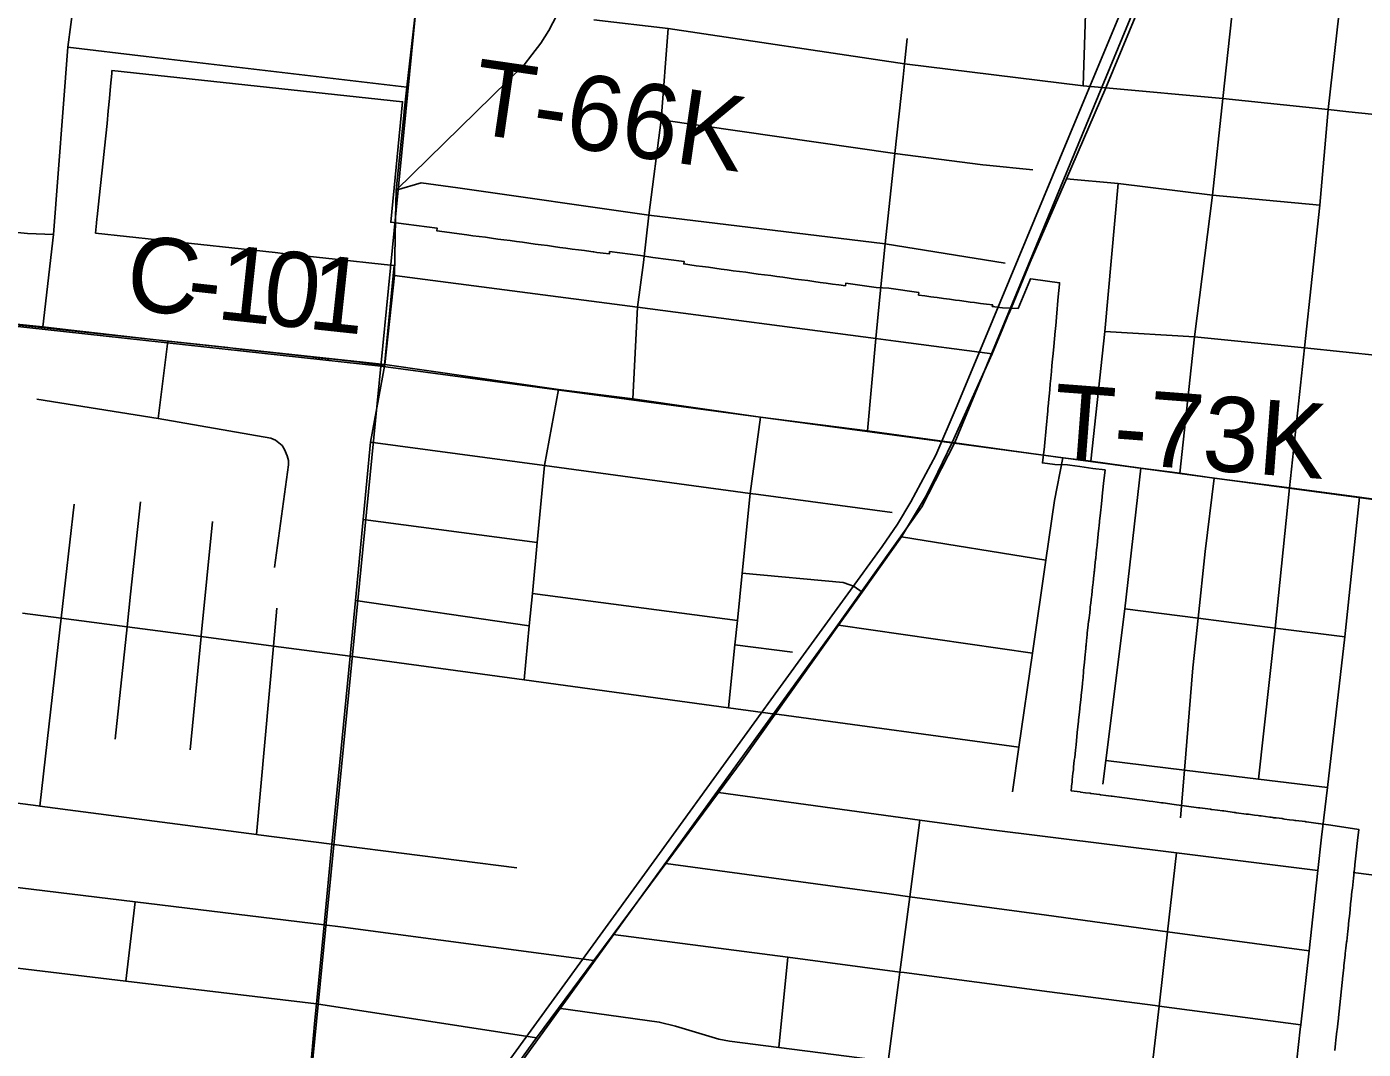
# Model space of a CAD drawing. Extents: x 0 to 34, y -3.9 to 26.2.
# Drawn here: x 5.706 to 6.718, y 17.55 to 18.325 of the extents above; entities that cross this region are included whole.
import ezdxf

# ---------------------------------------------------------------- set-up
doc = ezdxf.new("R2010")
doc.units = 0
for name, color, linetype in [('GM_X_City_Street', 7, 'Continuous'), ('GM_X_Corporation', 7, 'Continuous'), ('GM_X_County_Road', 7, 'Continuous'), ('GM_X_County_Road_Text', 7, 'Continuous'), ('GM_X_Rail_Line', 7, 'Continuous'), ('GM_X_Section', 7, 'Continuous'), ('GM_X_Township_Road', 7, 'Continuous'), ('GM_X_Township_Road_Text', 7, 'Continuous')]:
    doc.layers.add(name, color=color, linetype=linetype)

msp = doc.modelspace()

# ---------------------------------------------------------------- linework, layer by layer
at = {"layer": 'GM_X_City_Street'}
for p, q in [((5.8055, 18.0282), (5.8129, 18.0866)), ((5.9608, 17.9517), (6.0925, 17.9341)), ((6.3681, 17.9385), (6.4774, 17.9209)), ((5.9549, 17.8904), (6.0865, 17.8712)), ((6.0888, 17.8955), (6.244, 17.8752)), ((6.3205, 17.8715), (6.4673, 17.8504)), ((6.2421, 17.8567), (6.2856, 17.8512)), ((5.7812, 17.602), (5.7882, 17.6622)), ((6.2754, 17.5519), (6.2821, 17.6201))]:
    msp.add_line(p, q, dxfattribs=at)
for points in [[(6.1649, 18.0429), (6.1685, 18.1123), (6.173, 18.1463)], [(5.9844, 18.1365), (6.1685, 18.1123), (6.3487, 18.0887), (6.364, 18.0867), (6.4369, 18.0771)], [(6.3426, 18.0187), (6.3487, 18.0887), (6.3517, 18.1202)], [(6.0826, 17.8302), (6.0865, 17.8712), (6.0888, 17.8955), (6.0925, 17.9341), (6.098, 17.9924), (6.1086, 18.05)], [(5.7137, 18.0427), (5.8055, 18.0282), (5.8908, 18.0132), (5.8944, 18.0116), (5.8993, 18.0076), (5.9012, 18.0046), (5.9033, 17.9998), (5.9042, 17.9964), (5.9042, 17.993), (5.8936, 17.9152)], [(6.2373, 17.8091), (6.2421, 17.8567), (6.244, 17.8752), (6.2476, 17.911), (6.2537, 17.9713), (6.2615, 18.0292)], [(5.9664, 18.0102), (6.098, 17.9924), (6.2537, 17.9713), (6.2599, 17.9705), (6.3612, 17.9568)], [(6.4904, 17.9983), (6.4839, 17.9661), (6.4774, 17.9209), (6.4673, 17.8504), (6.4571, 17.7791), (6.4523, 17.7453)], [(5.716, 17.7346), (5.7312, 17.868), (5.7322, 17.8768), (5.742, 17.9633)], [(5.7731, 17.7852), (5.7821, 17.8703), (5.7847, 17.8951), (5.7921, 17.965)], [(5.8298, 17.7772), (5.8382, 17.8629), (5.8382, 17.8637), (5.8467, 17.9502)], [(6.2476, 17.911), (6.3241, 17.904), (6.329, 17.9022), (6.3325, 17.9008), (6.3384, 17.8967)], [(5.7029, 17.8806), (5.7322, 17.8768), (5.7821, 17.8703), (5.8382, 17.8629), (5.8929, 17.8558), (5.9508, 17.8482), (6.0826, 17.8302), (6.2373, 17.8091), (6.2727, 17.8042), (6.2756, 17.8039), (6.4571, 17.7791)], [(5.88, 17.713), (5.8929, 17.8558), (5.8955, 17.8844)], [(5.4423, 17.7675), (5.5662, 17.7527), (5.6896, 17.7381), (5.7147, 17.7348), (5.716, 17.7346), (5.88, 17.713), (5.8816, 17.7128), (5.9371, 17.7057), (5.9461, 17.7046), (6.077, 17.6878)], [(6.2298, 17.7449), (6.3821, 17.7239), (6.4324, 17.717), (6.5764, 17.6991), (6.6834, 17.6857)], [(6.3581, 17.5413), (6.367, 17.6089), (6.3745, 17.666), (6.3821, 17.7239)], [(5.438, 17.7046), (5.5591, 17.6899), (5.6908, 17.674), (5.7882, 17.6622), (5.9312, 17.6448), (5.9435, 17.6432), (6.1353, 17.6176)], [(6.6593, 17.4687), (6.663, 17.5023), (6.6636, 17.5075), (6.6701, 17.5656), (6.6704, 17.569), (6.6767, 17.6249), (6.6834, 17.6857), (6.6862, 17.7111)], [(6.549, 17.4743), (6.5555, 17.5161), (6.5632, 17.5831), (6.5696, 17.6395), (6.5764, 17.6991)], [(6.1899, 17.6911), (6.3588, 17.6682), (6.3745, 17.666), (6.478, 17.6519), (6.5696, 17.6395), (6.6767, 17.6249)], [(5.4304, 17.6437), (5.5522, 17.6292), (5.6971, 17.612), (5.7055, 17.611), (5.7812, 17.602), (5.9254, 17.5848), (6.092, 17.5592)], [(6.15, 17.6374), (6.2821, 17.6201), (6.367, 17.6089), (6.3702, 17.6085), (6.4803, 17.594), (6.5603, 17.5835), (6.5632, 17.5831), (6.6704, 17.569)], [(6.1086, 17.5816), (6.1848, 17.571), (6.1972, 17.568), (6.23, 17.558), (6.2379, 17.5567), (6.2754, 17.5519), (6.3581, 17.5413), (6.4712, 17.5269), (6.5519, 17.5165), (6.5555, 17.5161), (6.663, 17.5023)]]:
    msp.add_lwpolyline(points, dxfattribs=at)
at = {"layer": 'GM_X_Corporation'}
msp.add_lwpolyline([(5.6129, 18.1082), (5.8582, 18.0818), (5.8676, 18.0807), (5.877, 18.0797), (5.8958, 18.0776), (5.9186, 18.0751), (5.9193, 18.075), (5.9243, 18.0744), (5.9289, 18.0739), (5.9317, 18.0736), (5.9335, 18.0734), (5.9382, 18.0729), (5.9428, 18.0724), (5.9468, 18.0719), (5.956, 18.0709), (5.9656, 18.0698), (5.9769, 18.0686), (5.9842, 18.144), (5.9766, 18.1448), (5.9396, 18.1488), (5.9019, 18.1529), (5.8941, 18.1538), (5.805, 18.1634), (5.7582, 18.1685), (5.7589, 18.1761), (5.7592, 18.1793), (5.7594, 18.1808), (5.7599, 18.1856), (5.7609, 18.1951), (5.7619, 18.2045), (5.763, 18.2139), (5.764, 18.2233), (5.765, 18.2327), (5.766, 18.2421), (5.7669, 18.2516), (5.7678, 18.261), (5.7687, 18.2704), (5.7695, 18.2798), (5.7704, 18.2893), (5.7706, 18.2915), (5.9905, 18.2679), (5.9816, 18.1767), (5.9933, 18.1752), (6.0168, 18.1721), (6.0166, 18.1702), (6.0223, 18.1694), (6.0279, 18.1687), (6.0335, 18.1679), (6.0392, 18.1672), (6.0438, 18.1665), (6.0485, 18.1659), (6.0532, 18.1653), (6.0579, 18.1646), (6.0626, 18.164), (6.0673, 18.1634), (6.072, 18.1628), (6.0767, 18.1621), (6.0814, 18.1615), (6.0861, 18.1609), (6.0908, 18.1602), (6.0955, 18.1596), (6.1002, 18.159), (6.1049, 18.1583), (6.1095, 18.1577), (6.1142, 18.1571), (6.1189, 18.1564), (6.1236, 18.1558), (6.1283, 18.1552), (6.133, 18.1546), (6.1348, 18.1543), (6.1354, 18.1542), (6.1377, 18.1539), (6.14, 18.1536), (6.1424, 18.1533), (6.1471, 18.1527), (6.1473, 18.1545), (6.1707, 18.1514), (6.1801, 18.1501), (6.2036, 18.147), (6.2034, 18.1451), (6.2081, 18.1445), (6.2128, 18.1438), (6.2175, 18.1432), (6.2222, 18.1426), (6.2269, 18.1419), (6.2316, 18.1413), (6.2363, 18.1407), (6.2409, 18.14), (6.2456, 18.1394), (6.2503, 18.1388), (6.255, 18.1381), (6.2597, 18.1375), (6.2644, 18.1369), (6.2692, 18.1363), (6.2738, 18.1356), (6.2785, 18.135), (6.2832, 18.1344), (6.2879, 18.1337), (6.2926, 18.1331), (6.2973, 18.1325), (6.3019, 18.1318), (6.3066, 18.1312), (6.3113, 18.1306), (6.316, 18.1299), (6.3207, 18.1293), (6.3258, 18.1286), (6.326, 18.1305), (6.3491, 18.1274), (6.3585, 18.1268), (6.3813, 18.1235), (6.3811, 18.1215), (6.3858, 18.1209), (6.3904, 18.1203), (6.3926, 18.12), (6.3952, 18.1197), (6.3999, 18.119), (6.4045, 18.1184), (6.4092, 18.1178), (6.4121, 18.1174), (6.414, 18.1172), (6.4187, 18.1165), (6.4202, 18.1163), (6.4234, 18.1159), (6.428, 18.1153), (6.4326, 18.1147), (6.4373, 18.1141), (6.4369, 18.1129), (6.4446, 18.1118), (6.4564, 18.1113), (6.4578, 18.1145), (6.4616, 18.1236), (6.4653, 18.1327), (6.4658, 18.1339), (6.4678, 18.1336), (6.4879, 18.1309), (6.4878, 18.1297), (6.4869, 18.1203), (6.4864, 18.1145), (6.4861, 18.1108), (6.4855, 18.1052), (6.4852, 18.1014), (6.4847, 18.0961), (6.4845, 18.0942), (6.4834, 18.0826), (6.4829, 18.0773), (6.4825, 18.0731), (6.4821, 18.0683), (6.4817, 18.0637), (6.4812, 18.0587), (6.4812, 18.0584), (6.4808, 18.0543), (6.4804, 18.0501), (6.4799, 18.0448), (6.4797, 18.0431), (6.4794, 18.0398), (6.479, 18.0354), (6.4789, 18.034), (6.4777, 18.0208), (6.4764, 18.0071), (6.4764, 18.0069), (6.4749, 17.9944), (6.4843, 17.9932), (6.4938, 17.9929), (6.4956, 17.9927), (6.5032, 17.9917), (6.5131, 17.9903), (6.5223, 17.9891), (6.5212, 17.9788), (6.5202, 17.9693), (6.5201, 17.9684), (6.5196, 17.9637), (6.5193, 17.9609), (6.5191, 17.959), (6.5186, 17.9543), (6.5182, 17.9505), (6.5181, 17.9496), (6.5178, 17.9472), (6.5176, 17.9449), (6.5172, 17.9411), (6.5171, 17.9402), (6.5166, 17.9355), (6.5162, 17.9317), (6.5161, 17.9307), (6.5156, 17.926), (6.5152, 17.9222), (6.5151, 17.9213), (6.5146, 17.9166), (6.5142, 17.9128), (6.5141, 17.9119), (6.514, 17.9109), (6.5136, 17.9072), (6.5132, 17.9034), (6.5131, 17.9025), (6.5126, 17.8978), (6.5122, 17.894), (6.5121, 17.8931), (6.5115, 17.8884), (6.5111, 17.8853), (6.511, 17.8846), (6.5109, 17.8837), (6.5104, 17.879), (6.5102, 17.8774), (6.5099, 17.8752), (6.5098, 17.8743), (6.5093, 17.8696), (6.5088, 17.8658), (6.5087, 17.8652), (6.5087, 17.8649), (6.5084, 17.8617), (6.5083, 17.8602), (6.5079, 17.8563), (6.5078, 17.8555), (6.5077, 17.8539), (6.507, 17.8469), (6.5069, 17.846), (6.5065, 17.8413), (6.5061, 17.8375), (6.506, 17.8366), (6.5056, 17.8319), (6.5052, 17.828), (6.5051, 17.8272), (6.5047, 17.8225), (6.5043, 17.8186), (6.5042, 17.8177), (6.5037, 17.813), (6.5033, 17.8092), (6.5032, 17.8083), (6.5027, 17.8036), (6.5023, 17.7998), (6.5022, 17.7989), (6.5013, 17.7904), (6.5003, 17.7809), (6.4998, 17.7769), (6.4993, 17.7715), (6.499, 17.7693), (6.4985, 17.7641), (6.4983, 17.7621), (6.498, 17.7594), (6.4975, 17.7546), (6.4973, 17.7527), (6.497, 17.7499), (6.4969, 17.7493), (6.4966, 17.7462), (6.5034, 17.7453), (6.5037, 17.7452), (6.5074, 17.7447), (6.5109, 17.7443), (6.5115, 17.7442), (6.5182, 17.7433), (6.5184, 17.7433), (6.5187, 17.7432), (6.5192, 17.7432), (6.5229, 17.7427), (6.527, 17.7421), (6.5276, 17.7421), (6.535, 17.7411), (6.537, 17.7408), (6.5427, 17.7401), (6.5463, 17.7396), (6.5506, 17.739), (6.551, 17.739), (6.5557, 17.7383), (6.5585, 17.738), (6.5651, 17.7371), (6.5663, 17.737), (6.5745, 17.7358), (6.5839, 17.7346), (6.5929, 17.7334), (6.5935, 17.7334), (6.5941, 17.7333), (6.6022, 17.7322), (6.6027, 17.7321), (6.6029, 17.7321), (6.6032, 17.7321), (6.6074, 17.7315), (6.6111, 17.731), (6.6116, 17.731), (6.6121, 17.7309), (6.6122, 17.7309), (6.6201, 17.7298), (6.6209, 17.7297), (6.6215, 17.7296), (6.6217, 17.7296), (6.6291, 17.7286), (6.63, 17.7285), (6.6308, 17.7284), (6.6355, 17.7278), (6.6381, 17.7274), (6.6391, 17.7273), (6.6402, 17.7271), (6.6405, 17.7271), (6.6471, 17.7263), (6.6481, 17.7261), (6.6492, 17.726), (6.65, 17.7258), (6.6517, 17.7256), (6.6563, 17.7251), (6.657, 17.725), (6.658, 17.7248), (6.662, 17.7243), (6.665, 17.7239), (6.6659, 17.7237), (6.6666, 17.7236), (6.6737, 17.7228), (6.6742, 17.7227), (6.6749, 17.7226), (6.6835, 17.7215), (6.6838, 17.7214), (6.6932, 17.7201), (6.7143, 17.7169), (6.7134, 17.7086), (6.7124, 17.6993), (6.7114, 17.6901), (6.7113, 17.6894), (6.7103, 17.6801), (6.7095, 17.6724), (6.7092, 17.6699), (6.7086, 17.6641), (6.7082, 17.6605), (6.7078, 17.6564), (6.7072, 17.6511), (6.7069, 17.6481), (6.7062, 17.6417), (6.706, 17.6399), (6.7052, 17.6323), (6.7051, 17.6315), (6.7046, 17.627), (6.7046, 17.6269), (6.7041, 17.6229), (6.704, 17.6219), (6.7031, 17.6136), (6.703, 17.6123), (6.7021, 17.6038), (6.702, 17.6032), (6.701, 17.5939), (6.701, 17.5937), (6.7, 17.5842), (6.6999, 17.584), (6.6989, 17.5746), (6.6989, 17.5741), (6.6984, 17.5698), (6.6979, 17.5651), (6.6978, 17.5641), (6.6971, 17.5573), (6.6968, 17.5547), (6.6962, 17.5496)], dxfattribs=at)
at = {"layer": 'GM_X_County_Road'}
for p, q in [((5.9853, 18.1795), (5.9857, 18.201)), ((5.9844, 18.1365), (5.9853, 18.1795)), ((5.977, 18.069), (5.9844, 18.1365)), ((6.377, 18.0139), (6.4065, 18.0098)), ((6.4065, 18.0098), (6.459, 18.0026))]:
    msp.add_line(p, q, dxfattribs=at)
for points in [[(6.4488, 18.1059), (6.4496, 18.1078), (6.4657, 18.1464), (6.4931, 18.2096), (6.523, 18.2786), (6.5823, 18.4215), (6.6136, 18.497), (6.664, 18.6248), (6.6751, 18.6528), (6.6959, 18.7039), (6.7091, 18.7364), (6.7291, 18.7856), (6.8019, 18.9663), (6.8146, 18.9962), (6.8162, 18.9998)], [(5.9857, 18.201), (6.0827, 18.2958), (6.0884, 18.3035), (6.0953, 18.3124), (6.1012, 18.322), (6.1072, 18.3334), (6.1343, 18.3695), (6.1475, 18.3797), (6.1646, 18.3957), (6.1722, 18.4001), (6.18, 18.4058), (6.2308, 18.4428), (6.2973, 18.491), (6.3046, 18.4954), (6.3162, 18.5052), (6.3343, 18.5122), (6.3438, 18.5152)], [(6.523, 18.2786), (6.6114, 18.2703), (6.6913, 18.2622), (6.7068, 18.2604), (6.773, 18.2534), (6.8422, 18.2465), (6.9135, 18.2387), (7.0486, 18.2243)], [(5.6558, 18.1037), (5.7183, 18.0975), (5.7373, 18.0953)], [(5.9611, 17.3776), (5.9838, 17.4091), (6.0224, 17.4626), (6.0498, 17.5008), (6.0617, 17.5173), (6.0891, 17.5554), (6.092, 17.5592), (6.1086, 17.5816), (6.1353, 17.6176), (6.15, 17.6374), (6.1899, 17.6911), (6.2298, 17.7449), (6.2477, 17.769), (6.2727, 17.8042), (6.3205, 17.8715), (6.3384, 17.8967), (6.3681, 17.9385), (6.3863, 17.9689), (6.3919, 17.9797), (6.4065, 18.0098), (6.4369, 18.0771), (6.4449, 18.0964), (6.4488, 18.1059)], [(5.7373, 18.0953), (5.8129, 18.0866), (5.977, 18.069)], [(5.9044, 17.3782), (5.9051, 17.3854), (5.9085, 17.4182), (5.9191, 17.5198), (5.9217, 17.5443), (5.9242, 17.5725), (5.9254, 17.5848), (5.9312, 17.6448), (5.9371, 17.7057), (5.9508, 17.8482), (5.9549, 17.8904), (5.9608, 17.9517), (5.9664, 18.0102), (5.977, 18.069)], [(5.977, 18.069), (6.1086, 18.05), (6.1649, 18.0429), (6.2615, 18.0292), (6.3426, 18.0187), (6.377, 18.0139)], [(6.459, 18.0026), (6.4904, 17.9983), (6.5116, 17.9959), (6.5494, 17.9906), (6.579, 17.9867), (6.605, 17.983), (6.6619, 17.9756), (6.7148, 17.9684), (6.7418, 17.9647), (6.8606, 17.9483), (7.0165, 17.9261)]]:
    msp.add_lwpolyline(points, dxfattribs=at)
at = {"layer": 'GM_X_Rail_Line'}
for points in [[(5.7241, 16.9743), (5.8452, 17.029), (5.873, 17.0335), (5.8979, 17.2837), (6.0426, 17.4881), (6.3175, 17.8683), (6.3835, 17.9611), (6.4086, 18.0098), (6.517, 18.2722), (6.6945, 18.7013), (6.8945, 19.188), (6.9673, 19.2641), (7.0598, 19.3383), (7.1575, 19.4128), (7.1736, 19.4378), (7.1863, 19.6097), (7.204, 19.7377)], [(6.0705, 17.5409), (6.185, 17.6987), (6.2747, 17.8225), (6.3276, 17.8954), (6.3535, 17.9312), (6.3651, 17.9482), (6.3754, 17.9649), (6.3943, 18.0004), (6.4095, 18.0362), (6.4306, 18.0865), (6.4949, 18.2415), (6.5465, 18.3657)]]:
    msp.add_lwpolyline(points, dxfattribs=at)
at = {"layer": 'GM_X_Section'}
for points in [[(5.0852, 19.1785), (6.0727, 19.072), (5.9742, 18.0677), (4.9898, 18.1753)], [(6.0727, 19.072), (7.1209, 18.9374), (7.0185, 17.9275), (5.9742, 18.0677)], [(4.9898, 18.1753), (5.9742, 18.0677), (5.8743, 17.0495), (4.8928, 17.1679)], [(5.9742, 18.0677), (7.0185, 17.9275), (6.9147, 16.9222), (5.8743, 17.0495)]]:
    msp.add_lwpolyline(points, close=True, dxfattribs=at)
at = {"layer": 'GM_X_Township_Road'}
for p, q in [((5.7964, 18.3022), (5.7372, 18.3092)), ((5.9937, 18.279), (5.7964, 18.3022)), ((5.9857, 18.201), (5.9917, 18.26)), ((6.1864, 18.2543), (6.3632, 18.2288)), ((6.4325, 18.2199), (6.4675, 18.2164)), ((6.7314, 18.0756), (6.6732, 18.0815))]:
    msp.add_line(p, q, dxfattribs=at)
for points in [[(5.7263, 18.1674), (5.7066, 18.1682), (5.6942, 18.1694), (5.6828, 18.1711), (5.6753, 18.1756), (5.6691, 18.1811), (5.6651, 18.1865), (5.6623, 18.1943), (5.6611, 18.2039), (5.6761, 18.3491), (5.6939, 18.5267), (5.7184, 18.8118), (5.7292, 18.9224), (5.7299, 18.9306), (5.7303, 18.9358), (5.7334, 18.9429)], [(5.7183, 18.0975), (5.7263, 18.1674), (5.7372, 18.3092), (5.7441, 18.361), (5.7587, 18.5199), (5.7741, 18.6662)], [(5.9917, 18.26), (5.9918, 18.2609), (5.9937, 18.279), (6.0141, 18.458), (6.0213, 18.522), (6.0269, 18.6045), (6.0269, 18.6061), (6.0262, 18.6102)], [(6.5057, 18.2801), (6.5086, 18.3659), (6.52, 18.444), (6.5256, 18.5098)], [(6.715, 18.4829), (6.7077, 18.4075), (6.6913, 18.2622), (6.6849, 18.1897), (6.6732, 18.0815), (6.6619, 17.9756)], [(6.6274, 18.4169), (6.6114, 18.2703), (6.6035, 18.1972), (6.5899, 18.0899), (6.579, 17.9867)], [(6.1354, 18.33), (6.1917, 18.3233), (6.3705, 18.2966), (6.5057, 18.2801), (6.523, 18.2786)], [(6.1917, 18.3233), (6.1864, 18.2543), (6.1769, 18.1821), (6.173, 18.1463)], [(6.3725, 18.3159), (6.3705, 18.2966), (6.3694, 18.2865)], [(6.3694, 18.2865), (6.3632, 18.2288), (6.3559, 18.1603), (6.3517, 18.1202)], [(6.3632, 18.2288), (6.4298, 18.2202), (6.4325, 18.2199)], [(6.4467, 18.1457), (6.3559, 18.1603), (6.1769, 18.1821), (6.0323, 18.2027), (6.0046, 18.2065), (5.9857, 18.201)], [(6.4931, 18.2096), (6.5322, 18.2061), (6.6035, 18.1972), (6.6849, 18.1897)], [(6.5116, 17.9959), (6.522, 18.0939), (6.5322, 18.2061)], [(6.6732, 18.0815), (6.5899, 18.0899), (6.522, 18.0939)], [(6.5494, 17.9906), (6.5372, 17.884), (6.5229, 17.7692), (6.5207, 17.7513)], [(6.5795, 17.7258), (6.5824, 17.7619), (6.5888, 17.8392), (6.5928, 17.8768), (6.5981, 17.9275), (6.605, 17.983)], [(6.6619, 17.9756), (6.651, 17.8692), (6.6384, 17.7551)], [(6.6862, 17.7111), (6.6906, 17.7487), (6.7038, 17.8627), (6.7148, 17.9684)], [(6.5372, 17.884), (6.5928, 17.8768), (6.651, 17.8692), (6.7038, 17.8627)], [(6.5229, 17.7692), (6.5824, 17.7619), (6.6384, 17.7551), (6.6906, 17.7487)], [(6.71, 17.6844), (6.7358, 17.6811), (6.746, 17.6799), (6.7615, 17.6805), (6.7771, 17.6812), (6.8272, 17.6758), (6.887, 17.6663)]]:
    msp.add_lwpolyline(points, dxfattribs=at)

# ---------------------------------------------------------------- texts
at = {"layer": 'GM_X_County_Road_Text'}
for s, rotation, p in [('C', 353.5951, (5.7794, 18.1113)), ('1', 353.8719, (5.8487, 18.1036)), ('0', 353.8802, (5.8833, 18.0999)), ('1', 353.8804, (5.9178, 18.0962)), ('-', 353.8022, (5.8257, 18.1061))]:
    msp.add_text(s, height=0.0568, rotation=rotation, dxfattribs=at).set_placement(p)
at = {"layer": 'GM_X_Township_Road_Text'}
for s, rotation, p in [('T-66K', 351.7243, (6.0408, 18.2445)), ('T-73K', 355.6607, (6.4811, 17.9979))]:
    msp.add_text(s, height=0.05682, rotation=rotation, dxfattribs=at).set_placement(p)

doc.saveas('drawing.dxf')
